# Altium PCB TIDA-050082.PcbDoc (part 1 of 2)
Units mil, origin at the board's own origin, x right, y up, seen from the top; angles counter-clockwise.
Board outline 3622.05 x 2047.24 mil, 6 copper layers (Top Layer, Signal Layer 1, Signal Layer 2, Signal Layer 3, Signal Layer 4, Bottom Layer), stack 61.4 mil thick; 61 components, 29 nets, 139 pads, 38 vias.
Unrouted connection lines stored in the file: 18.
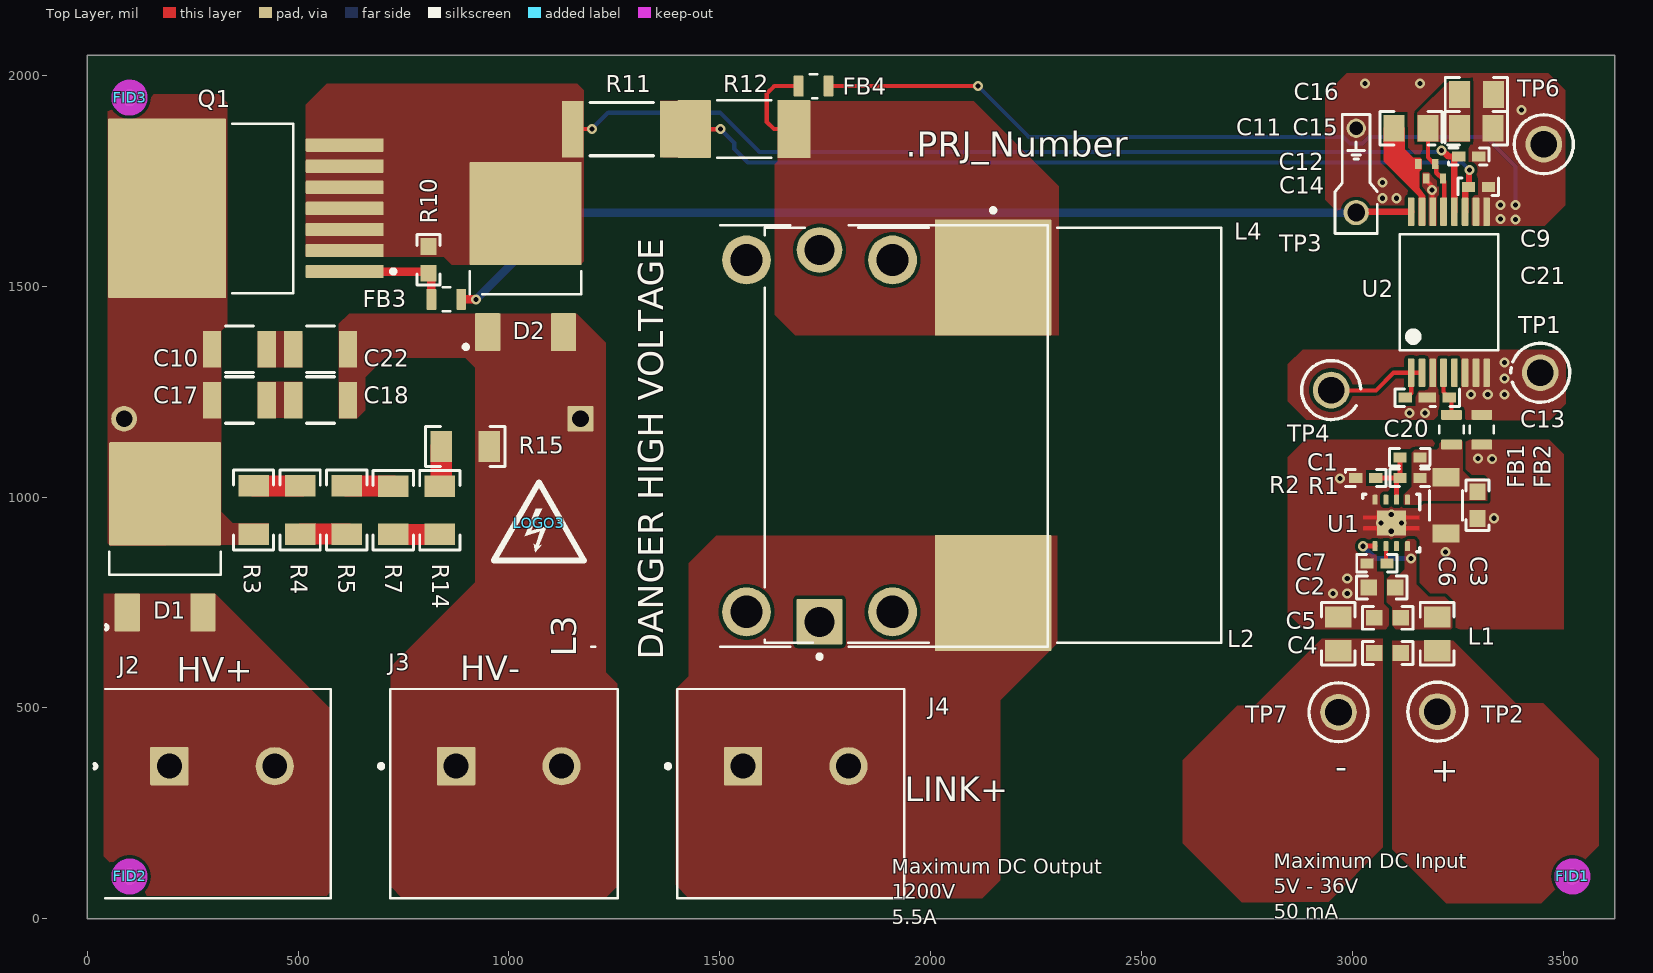
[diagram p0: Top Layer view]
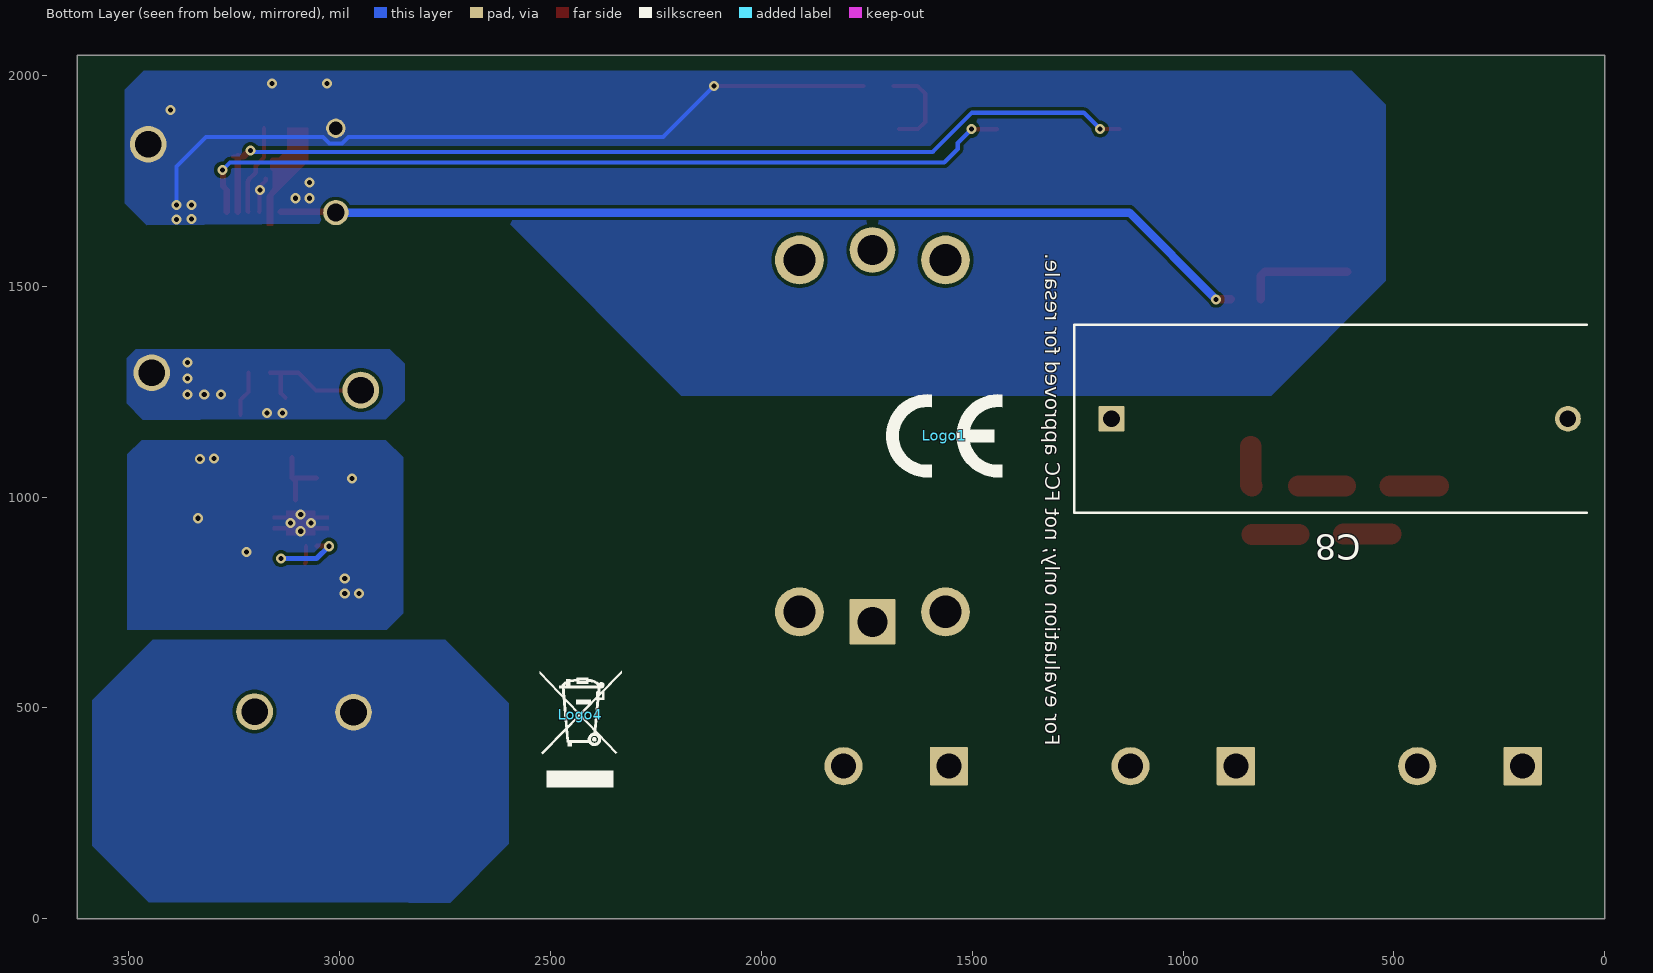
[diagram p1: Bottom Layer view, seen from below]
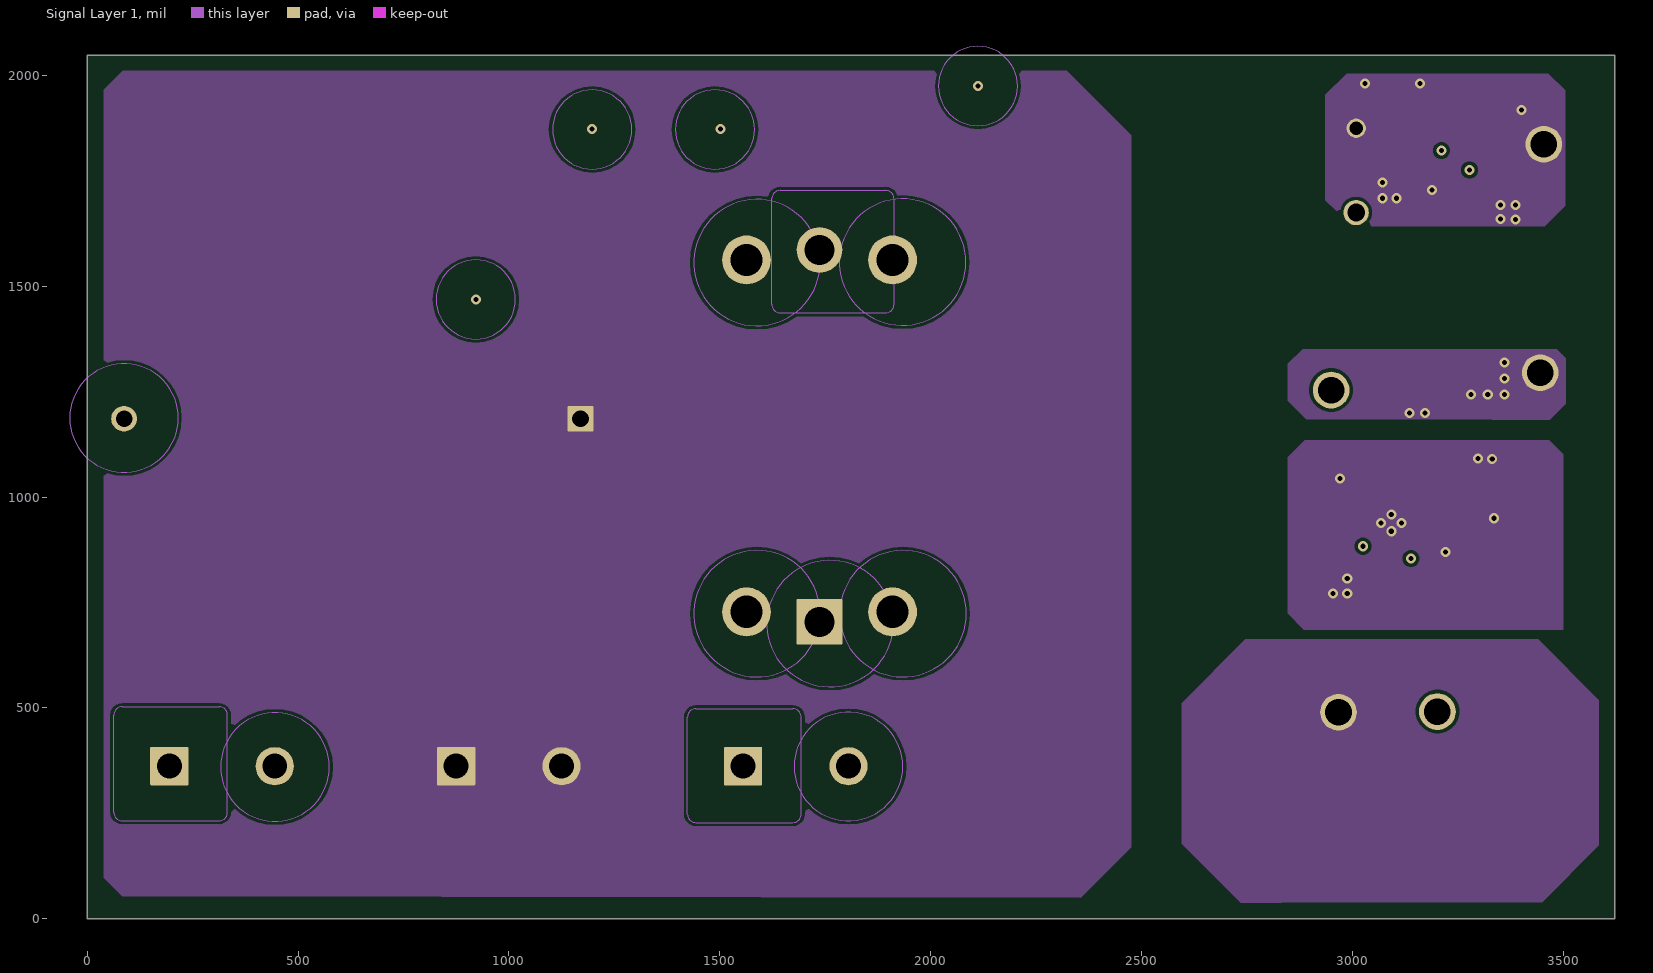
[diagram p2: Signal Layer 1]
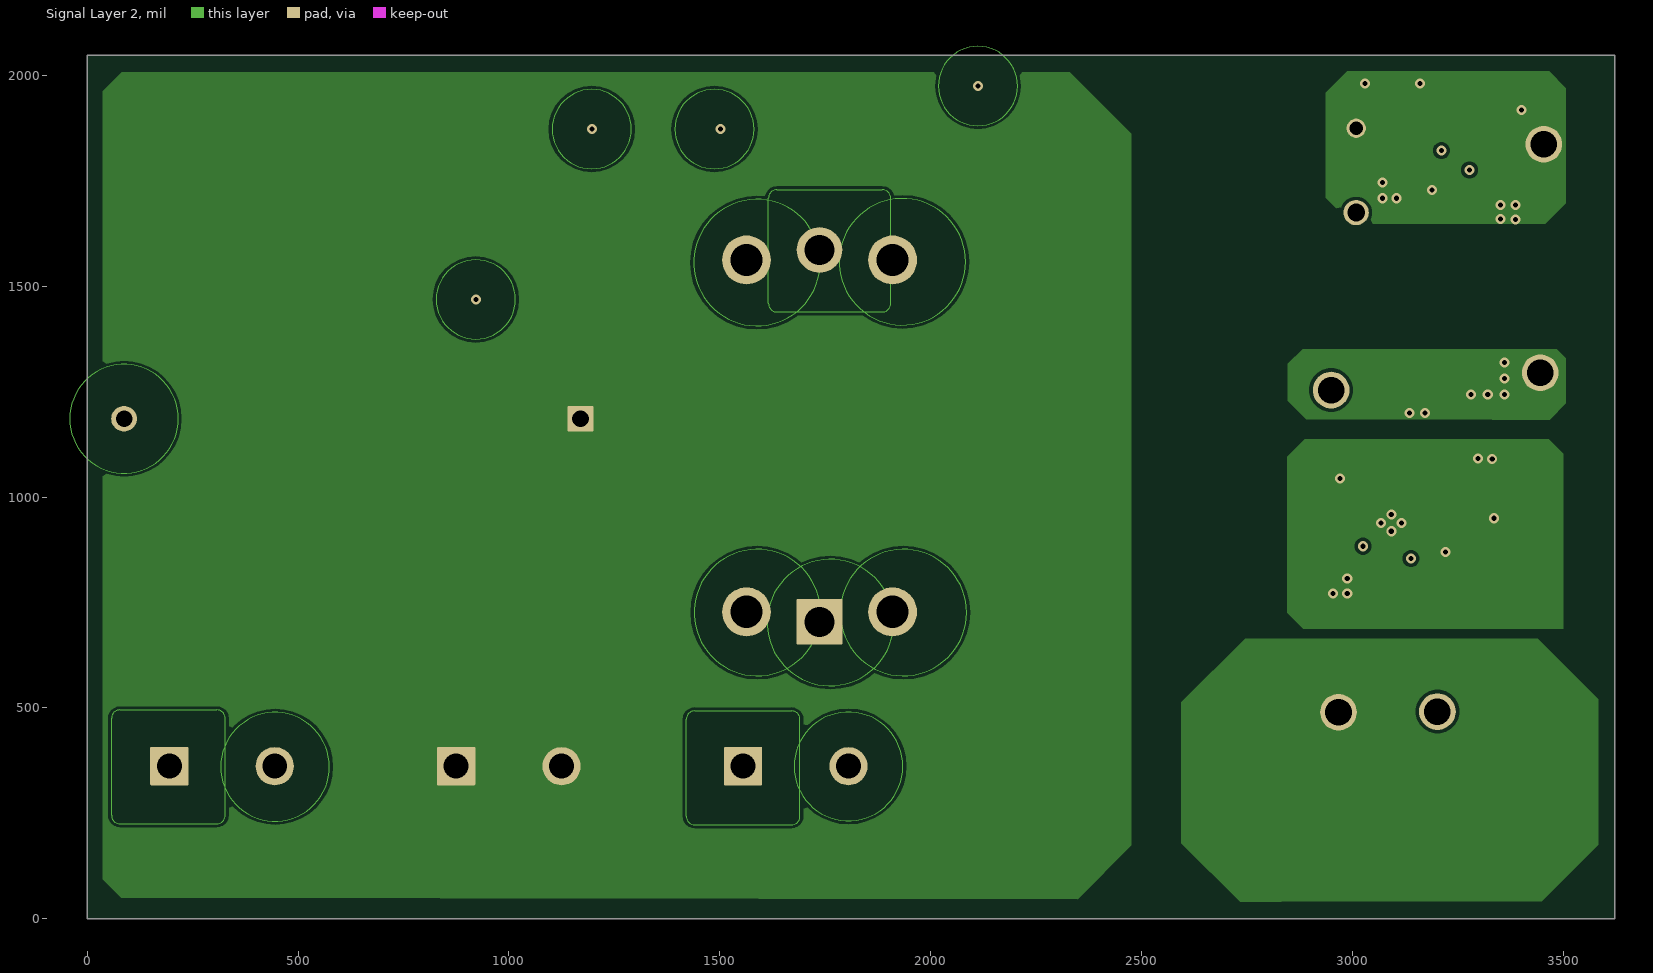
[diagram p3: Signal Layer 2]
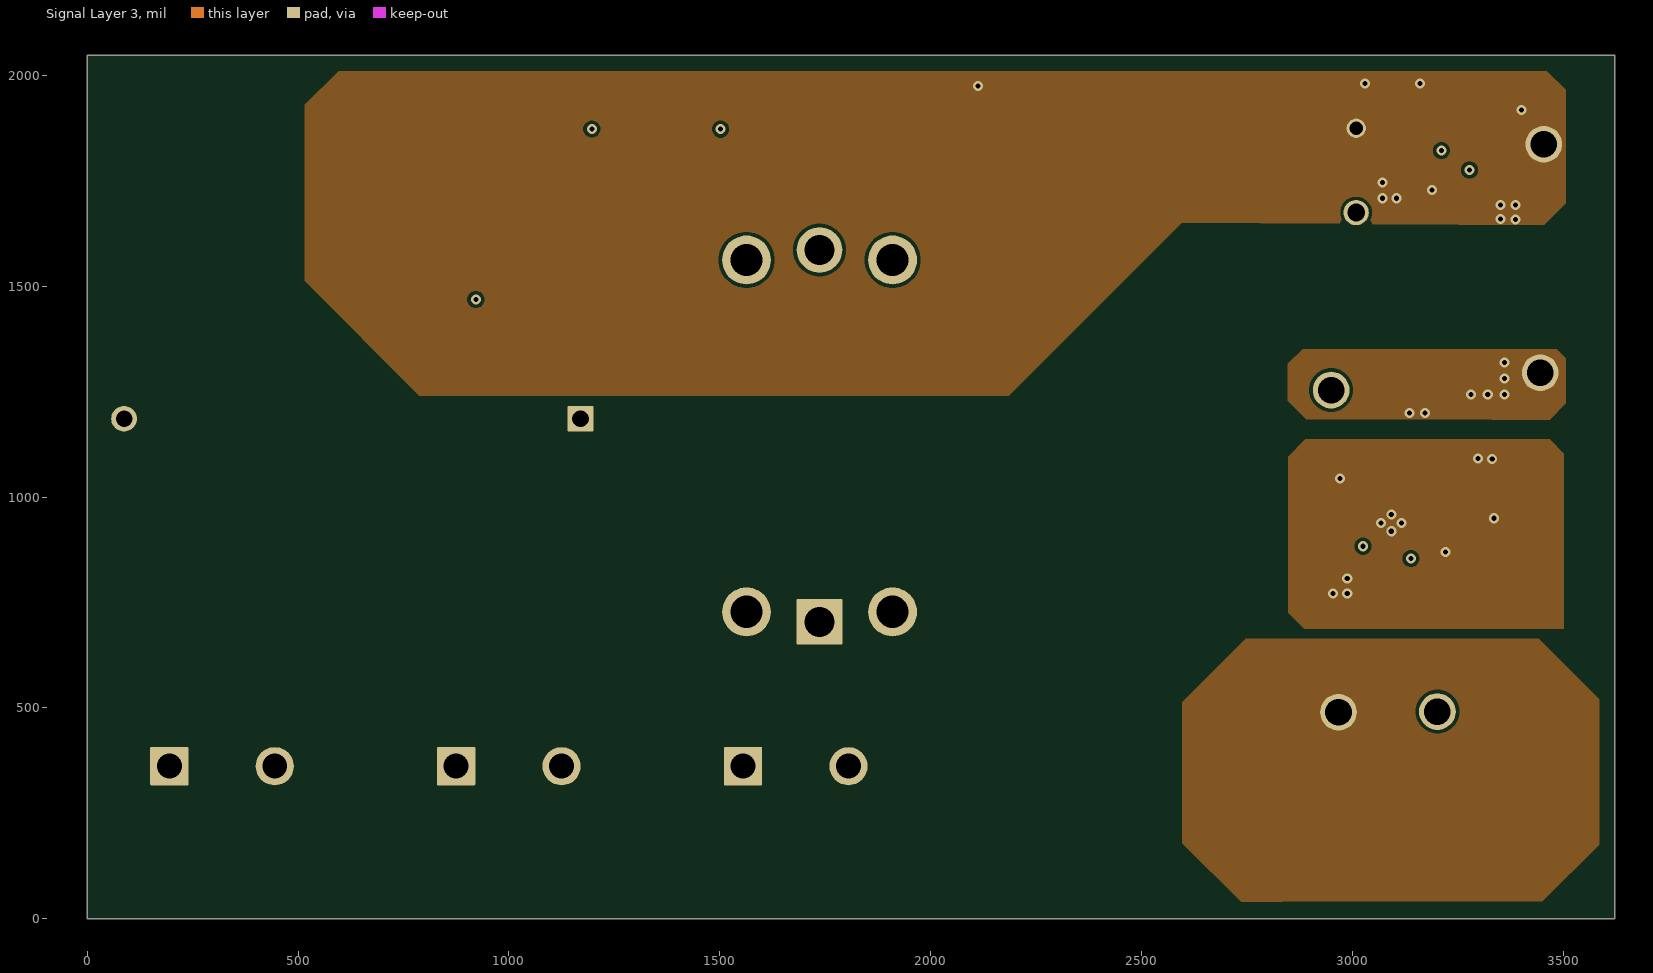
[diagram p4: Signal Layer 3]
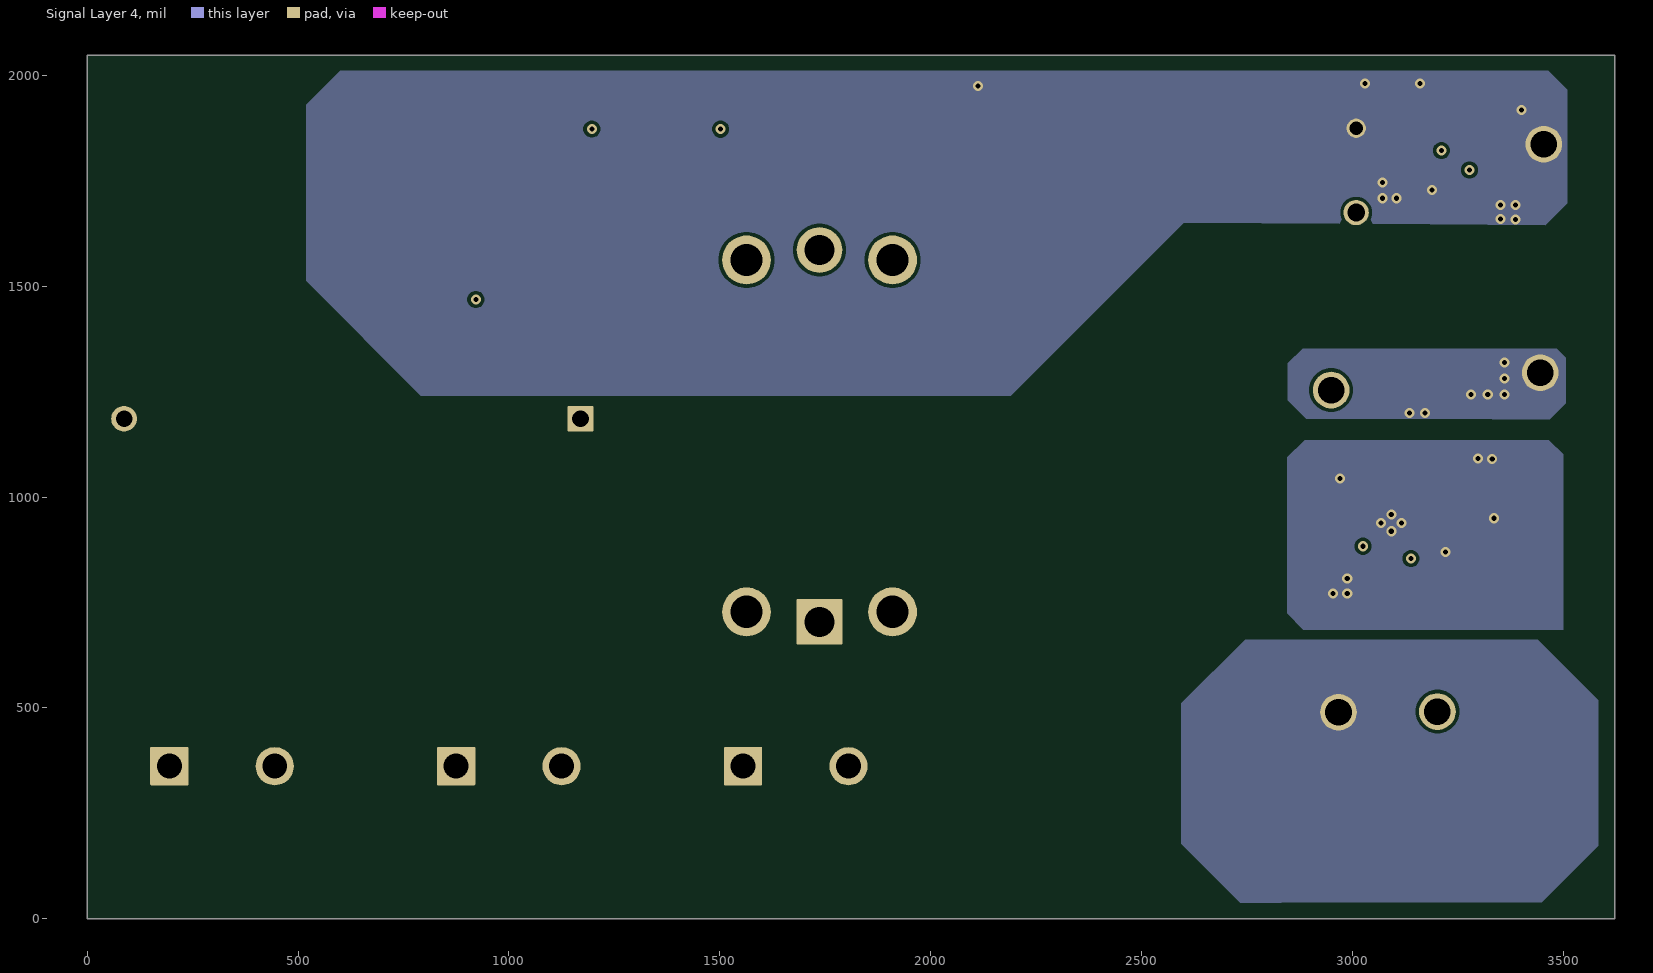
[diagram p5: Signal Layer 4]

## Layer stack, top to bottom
Top Solder: solder mask 0.5, Solder Resist, Dk 3.5
Top Layer: signal copper 2.8
Dielectric 1: prepreg 7, FR-4 High Tg, Dk 4.2
Signal Layer 1: signal copper 1.4
Dielectric 2: core 14, FR-4 High Tg, Dk 4.2
Signal Layer 2: signal copper 1.4
Dielectric 4: prepreg 8.2, FR-4 High Tg, Dk 4.2
Signal Layer 3: signal copper 1.4
Dielectric 5: core 14, FR-4 High Tg, Dk 4.2
Signal Layer 4: signal copper 1.4
Dielectric 3: prepreg 7, FR-4 High Tg, Dk 4.2
Bottom Layer: signal copper 2.8
Bottom Solder: solder mask 0.5, Solder Resist, Dk 3.5

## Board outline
0,0 3622.05,0 3622.05,2047.24 0,2047.24

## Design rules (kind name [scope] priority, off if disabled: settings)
BoardOutlineClearance [All] p1: gap=11.81 ignorepadtopadclearanceinfootprint=FALSE except(15.75: Arc-SplitBarrior Arc-SplitContinuation Track-SplitBarrior Track-SplitContinuation SMDPad-SplitBarrior SMDPad-SplitContinuation THPad-SplitBarrior THPad-SplitContinuation Via-SplitBarrior Via-SplitContinuation Fill-SplitBarrior Fill-SplitContinuation Poly-SplitBarrior Poly-SplitContinuation Region-SplitBarrior Region-SplitContinuation Text-SplitBarrior Text-SplitContinuation)
Clearance "Clearance Different Nets" [All] p1: gap=7.87 ignorepadtopadclearanceinfootprint=FALSE except(3.5: Arc-Arc Arc-Track Arc-SMDPad Track-Track Track-SMDPad; 5: SMDPad-SMDPad SMDPad-Via THPad-Via Via-Via; 10: Arc-Via Arc-Text Track-Via Track-Text SMDPad-Text THPad-Text Via-Text Fill-Text Poly-Text Region-Text Text-Text; 19.68: THPad-THPad Via-Hole)
Clearance "Clearance Same Nets" [All] p2: gap=7.87 ignorepadtopadclearanceinfootprint=FALSE except(3.5: Arc-Arc Arc-Track Arc-SMDPad Track-Track Track-SMDPad SMDPad-SMDPad; 5: SMDPad-Via THPad-Via; 10: Arc-Via Arc-Text Track-Via Track-Text SMDPad-Text THPad-Text Via-Via Via-Text Fill-Text Poly-Text Region-Text Text-Text)
Clearance "Clearance Bottom Layer" [OnLayer('Bottom Layer')] p3: gap=8 ignorepadtopadclearanceinfootprint=TRUE except(10: Arc-Text Track-Text SMDPad-Text THPad-Text Via-Text Fill-Text Poly-Text Region-Text Text-Text)
Clearance "Clearance Top Layer" [OnLayer('Top Layer')] p4: gap=8 ignorepadtopadclearanceinfootprint=TRUE except(10: Arc-Text Track-Text SMDPad-Text THPad-Text Via-Text Fill-Text Poly-Text Region-Text Text-Text)
HoleSize [All] p1: absolutevalues=TRUE maxlimit=248.03 minlimit=7.87 maxpercent=80.000 minpercent=20.000
MinimumAnnularRing [All] p1: minimumring=5.91
MinimumSolderMaskSliver [All] p1: minsoldermaskwidth=3.94
PlaneConnect [All] p1: planeconnectstyle=Direct reliefexpansion=20 reliefentries=4 reliefconductorwidth=10 reliefairgap=10
PolygonConnect PolygonConnect_1 [All] p1: connectstyle=Direct reliefconductorwidth=20 reliefentries=4 polygonreliefangle="90 Angle" airgapwidth=10
RoutingCorners [All] p1: cornerstyle=Round minsetback=100 maxsetback=100
RoutingVias [All] p1: holewidth=19.68 width=39.37 viastyle="Through Hole" minholewidth=7.87 minwidth=13.78 maxholewidth=39.37 maxwidth=78.74
SilkToBoardRegionClearance [Not ((IsComment or IsDesignator) And (Hide <> 'False')) and not InRegion(1000,500,4000,800)] p1:
SilkToSilkClearance [All] p1: silktosilkclearance=3.94
SilkToSolderMaskClearance [IsPad] p1: minsilkscreentomaskgap=3.94 clearancetoexposedcopper=TRUE
SolderMaskExpansion [All] p1: expansion=4 istentingtop=FALSE
SupplyNets "Schematic Supply Nets_4" [InNet('VSSS')] p1: voltage=0.000
SupplyNets "Schematic Supply Nets_3" [InNet('-HV')] p2: voltage=0.000
SupplyNets "Schematic Supply Nets_2" [InNet('+IN')] p3: voltage=0.000
SupplyNets "Schematic Supply Nets_1" [InNet('VSSP')] p4: voltage=0.000
SupplyNets "Schematic Supply Nets" [InNet('V_cap')] p5: voltage=0.000
Width [All] p1: maxlimit=100 minlimit=3.5 preferedwidth=15
23 further rules are at their usual default settings.

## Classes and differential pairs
component class TIDA-050082-Hardware: FID1 FID2 FID3 Logo1 Logo2 LOGO3 Logo4
component class FiducialMark: FID1 FID2 FID3
component class TIDA-050082: C1 C2 C3 C4 C5 C6 C7 C8 C9 C10 C11 C12 C13 C14 C15 C16 C17 C18 C20 C21 C22 D1 D2 FB1 FB2 FB3 FB4 J2 J3 J4 L1 L2 L3 L4 Q1 R1 R2 R3 R4 R5 R7 R10 R11 R12 R14 R15 SH-J? TP1 TP2 TP3 TP4 TP6 TP7 U1 U2 U?

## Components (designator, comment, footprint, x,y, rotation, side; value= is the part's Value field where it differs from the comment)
C1 "GRM155R71E103KA01D" 0402 3136.83,1094.24 r180 top value=0.01uF
C2 "CGA3E2X7R1H104K080AA" 0603 3070.36,785.66 r180 top value=0.1uF
C3 "CGA3E2X7R1H104K080AA" 0603 3297.36,980.66 r270 top value=0.1uF
C4 "GCM188R71H103KA37D" 0603 3083.9,630.25 r180 top value=0.01uF
C5 "GRT188R61E106ME13D" 0603 3083.9,713.64 r180 top value=10uF
C6 "GRM31CR71E106KA12L" 1206_180 3222.36,980.24 r270 top value=10uF
C7 "GRM155R71E103KA01D" 0402 3058.67,842.8 r180 top value=0.01uF
C8 "C4AQSBU4100A1WJ" FP-C4AQSBU4100A1WJ_RADIAL-MFG 628.36,1185.66 r180 bottom value=1µF
C9 "885012205044" 0402 3276.36,1807.66 r0 top value=1000pF
C10 "C1210C104KBRAC7800" 1210_280 360.48,1350.66 r0 top value=0.1uF
C11 "GRM21BZ71E106KE15L" 0805_HV 3139.36,1874.66 r0 top value=10uF
C12 "GRM155R71H103KA88D" 0402S 3176.86,1789.59 r0 top value=0.01uF
C13 "GRM155R71E103KA01D" 0402 3206.36,1235.66 r180 top value=0.01uF
C14 "GRM155R71H103KA88D" 0402S 3195.36,1755.33 r180 top value=0.01uF
C15 "GRM21BZ71E106KE15L" 0805_HV 3293.92,1874.66 r0 top value=10uF
C16 "GRM21BR61E226ME44L" 0805_HV 3294.58,1954.66 r0 top value=22uF
C17 "C1210C104KBRAC7800" 1210_280 360.48,1229.88 r0 top value=0.1uF
C18 "C1210C104KBRAC7800" 1210_280 553.39,1229.88 r0 top value=0.1uF
C20 "GRM155R71E103KA01D" 0402 3149.36,1235.66 r0 top value=0.01uF
C21 "885012205044" 0402 3299.36,1735.66 r0 top value=1000pF
C22 "C1210C104KBRAC7800" 1210_280 553.36,1350.66 r0 top value=0.1uF
D1 "VS-8EWF12SLHM3" FP-VS-8EWF12SLHM3_DPAK-MFG 184.36,905.66 r0 top
D2 "VS-8EWF12SLHM3" FP-VS-8EWF12SLHM3_DPAK-MFG 1039.36,1570.66 r0 top
FB1 "BLM21HE802SH1L" FP-BLM21HE802SH1L_0805-MFG 3235.36,1159.66 r90 top
FB2 "BLM21HE802SH1L" FP-BLM21HE802SH1L_0805-MFG 3307.36,1159.66 r90 top
FB3 "BLM21HE802SH1L" FP-BLM21HE802SH1L_0805-MFG 851.36,1468.66 r180 top
FB4 "BLM21HE802SH1L" FP-BLM21HE802SH1L_0805-MFG 1722.36,1974.66 r180 top
FID1 "Fiducial" Fiducial10-20 3522.05,100 r90 top
FID2 "Fiducial" Fiducial10-20 100,100 r90 top
FID3 "Fiducial" Fiducial10-20 100,1947.24 r90 top
J2 "691250610002" FP-691250610002_CONN_TERM_BLOCK2-MFG 307.55,296.66 r0 top
J3 "691250610002" FP-691250610002_CONN_TERM_BLOCK2-MFG 987.95,296.66 r0 top
J4 "691250610002" FP-691250610002_CONN_TERM_BLOCK2-MFG 1668.36,296.66 r0 top
L1 "BLM21AG102SN1D" 0805_HV 3201.31,675.4 r90 top value="1000 ohm"
L2 "BLM21AG102SN1D" 0805_HV 2966.61,675.4 r90 top value="1000 ohm"
L3 "ZG3718" FP-ZG3718_PTH6-MFG 1736.58,1145 r90 top value=100uH
L4 "ZF3172-AE" FP-ZF3172-AE_SMD2-MFG 2148.36,1146.66 r270 top value=100uH
Logo1 "CE Mark" CE_Mark_5mm 1566.36,1145 r180 bottom
Logo2 "FCC disclaimer" FCC_disclaimer 4048.02,567.94 r90 top
LOGO3 "DANGER HIGH VOLTAGE" IEC_HighVoltage_Small 1071,937.69 r0 top
Logo4 "WEEE logo" WEEE_Minimum 2430,483.63 r180 bottom
Q1 "AIMBG120R160M1XTMA1" FP-AIMBG120R160M1XTMA1_TO263-7-MFG 302.36,1684.66 r90 top
R1 "ERJ-2RKF2943X" 0402 3137.15,1045.66 r0 top value=294k
R2 "ERJ-2RKF9092X" 0402 3032.1,1045.11 r0 top value=90.9k
R3 "CRCW1206180KJNEA" 1206 394.3,969.19 r270 top value=180k
R4 "CRCW1206180KJNEA" 1206 504.71,969.19 r90 top value=180k
R5 "CRCW1206180KJNEA" 1206 615.13,969.19 r270 top value=180k
R7 "CRCW1206180KJNEA" 1206 725.54,968.66 r90 top value=180k
R10 "ERJ-3GEYJ104V" 0603 809.36,1562.66 r270 top value=100k
R11 "WSL2512R0600FEA" 2512 1267.61,1872.66 r180 top value=0.06
R12 "TLRP3A20CR080FTE" FP-TLRP3A20CR080FTE_2512-MFG 1557.61,1872.66 r180 top value=80m
R14 "CRCW1206180KJNEA" 1206 835.95,968.66 r270 top value=180k
R15 "CRCW1206180KJNEA" 1206 896.36,1119.66 r180 top value=180k
TP1 "5011" Keystone5011 3446,1294.72 r0 top
TP2 "" Keystone5010 3202,491 r0 top
TP3 "TESTPOINT_PIGTAIL" TESTPOINT_PIGTAIL 3009.36,1674.66 r180 top
TP4 "EN" Keystone5014 2950,1253.66 r0 top
TP6 "5011" Keystone5011 3454.36,1836.66 r0 top
TP7 "5011" Keystone5011 2967.36,489.64 r0 top
U1 "TPS7A4901DRBR" DRB0008A 3092.58,938.49 r270 top
U2 "TPSI31P1QDVXRQ1" DVX0016A-MFG 3229.36,1485.66 r90 top

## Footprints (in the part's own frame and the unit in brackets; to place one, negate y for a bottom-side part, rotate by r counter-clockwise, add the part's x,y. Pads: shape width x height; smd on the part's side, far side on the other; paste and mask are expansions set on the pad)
0402 [mm] "0402 from SM-752 data"
  rect 0.8x0.6 smd: 1(-0.6,0) 2(0.6,0)
  silkscreen extent -1.22,-0.52 1.22,0.52, body extent -0.55,-0.3 0.55,0.3, height 0.6
0402S [mil] "Based on C0402S footprint from PADS legacy"
  rect 15x24 smd: 1(-20,0) 2(20,0)
  body extent -22,-12 22,12, height 24
0603 [mm] "0603 from SM-752 data"
  rect 1x0.95 smd: 1(-0.8,0) 2(0.8,0)
  silkscreen extent -1.52,-0.69 1.52,0.69, body extent -0.87,-0.47 0.87,0.47, height 1
0805_HV [mil] "0805 with 30mil clearance between pads"
  rect 50x63 smd: 1(-40,0) 2(40,0)
  silkscreen extent -74,-40 74,40, body extent -43,-29 43,29, height 57
1206 [mm] "1206 from SM-752 data"
  rect 1.3x1.85 smd: 1(-1.45,0) 2(1.45,0)
  silkscreen extent -2.4,-1.21 2.4,1.21, body extent -1.7,-0.9 1.7,0.9, height 1.35
1206_180 [mm] "1206_180"
  rect 1.1x1.6 smd: 1(-1.7,0) 2(1.7,0)
  silkscreen extent -0.9,-1 0.9,1, body extent -1.75,-0.95 1.75,0.95, height 1.8
1210_280 [mm] "SMD, 2-Leads, Body 3.6x2.8mm, Height 2.8mm"
  rect 1.1x2.2 smd: 1(-1.65,0) 2(1.65,0)
  silkscreen extent -0.84,-1.4 0.84,1.4, body extent -1.8,-1.4 1.8,1.4, height 2.8
2512 [mm] "Chip Resistor, Body 6.3x3.2mm, IPC Medium Density"
  rect 1.3x3.4 smd: 1(-2.95,0) 2(2.95,0)
  silkscreen extent -1.9,-1.6 1.9,1.6, body extent -3.22,-1.67 3.22,1.67, height 0.71
CE_Mark_5mm [mil] "Minimum text height for CE Mark"
  silkscreen extent -138,-98 138,98
DRB0008A [mm] "VSON-8"
  rrect32% 0.6x0.31 smd: 1(-1.4,0.975) 2(-1.4,0.325) 3(-1.4,-0.325) 4(-1.4,-0.975) 5(1.4,-0.975) 6(1.4,-0.325) 7(1.4,0.325) 8(1.4,0.975)
  rrect7% 1.5x1.75 smd paste-0.75: 9(0,0)
  Top Layer region: -0.7,-0.875 -0.49,-0.875 -0.471,-0.879 -0.455,-0.89 -0.444,-0.906 -0.44,-0.925 -0.44,-0.925 -0.44,-1.65 -0.436,-1.669 -0.425,-1.685 -0.409,-1.696 -0.39,-1.7 -0.39,-1.7 -0.26,-1.7 -0.241,-1.696 -0.225,-1.685 -0.214,-1.669 -0.21,-1.65 -0.21,-1.65 -0.21,-0.925 -0.206,-0.906 -0.195,-0.89 -0.179,-0.879 -0.16,-0.875 -0.16,-0.875 0.16,-0.875 0.179,-0.879 0.195,-0.89 0.206,-0.906 0.21,-0.925 0.21,-0.925 0.21,-1.65 0.21,-1.65 0.214,-1.669 0.225,-1.685 0.241,-1.696 0.26,-1.7 0.26,-1.7 0.39,-1.7 0.409,-1.696 0.425,-1.685 0.436,-1.669 0.44,-1.65 0.44,-1.65 0.44,-0.925 0.444,-0.906 0.455,-0.89 0.471,-0.879 0.49,-0.875 0.49,-0.875 0.7,-0.875 0.719,-0.871 0.735,-0.86 0.746,-0.844 0.75,-0.825 0.75,-0.825 0.75,0.825 0.746,0.844 0.735,0.86 0.719,0.871 0.7,0.875 0.7,0.875 0.49,0.875 0.471,0.879 0.455,0.89 0.444,0.906 0.44,0.925 0.44,0.925 0.44,1.65 0.436,1.669 0.425,1.685 0.409,1.696 0.39,1.7 0.39,1.7 0.26,1.7 0.241,1.696 0.225,1.685 0.214,1.669 0.21,1.65 0.21,1.65 0.21,1.65 0.21,0.925 0.206,0.906 0.195,0.89 0.179,0.879 0.16,0.875 0.16,0.875 -0.16,0.875 -0.179,0.879 -0.195,0.89 -0.206,0.906 -0.21,0.925 -0.21,0.925 -0.21,1.65 -0.214,1.669 -0.225,1.685 -0.241,1.696 -0.26,1.7 -0.26,1.7 -0.39,1.7 -0.409,1.696 -0.425,1.685 -0.436,1.669 -0.44,1.65 -0.44,1.65 -0.44,0.925 -0.444,0.906 -0.455,0.89 -0.471,0.879 -0.49,0.875 -0.49,0.875 -0.7,0.875 -0.719,0.871 -0.735,0.86 -0.746,0.844 -0.75,0.825 -0.75,0.825 -0.75,-0.825 -0.746,-0.844 -0.735,-0.86 -0.719,-0.871 -0.7,-0.875
  silkscreen extent -1.73,-1.73 1.73,1.73, body extent -1.5,-1.5 1.5,1.5, height 0.77
DVX0016A-MFG [mm]
  rrect24% 1.7x0.41 smd paste+0 mask+0: 1(-4.85,2.275) 2(-4.85,1.625) 3(-4.85,0.975) 4(-4.85,0.325) 5(-4.85,-0.325) 6(-4.85,-0.975) 7(-4.85,-1.625) 8(-4.85,-2.275) 9(4.85,-2.275) 10(4.85,-1.625) 11(4.85,-0.975) 12(4.85,-0.325) 13(4.85,0.325) 14(4.85,0.975) 15(4.85,1.625) 16(4.85,2.275)
  silkscreen extent -3.5,-2.98 3.5,2.98, body extent -5.8,-3.22 5.8,3.22, height 0.25
FCC_disclaimer [mil]
Fiducial10-20 [mm]
  round 1 smd mask+0.5: 1(0,0)
  Top Layer keep-out circle w1.178: c0,0 r0.5
FP-691250610002_CONN_TERM_BLOCK2-MFG [mm]
  rrect4% 2.3x2.3 hole 1.5 paste-2539.97 mask+0: 1(-2.875,1.65)
  round 2.3 hole 1.5 paste-2539.97 mask+0: 2(3.475,1.65)
  silkscreen extent -7.39,-6.3 6.85,6.3, body extent -6.95,-6.4 6.95,6.4, height 0.25
FP-AIMBG120R160M1XTMA1_TO263-7-MFG [mm] "Recommended Land Pattern"
  rrect13% 0.8x4.7 smd paste-1000 mask+0: 1(-3.81,-7.825) 2(-2.54,-7.825) 3(-1.27,-7.825) 4(0,-7.825) 5(1.27,-7.825) 6(2.54,-7.825) 7(3.81,-7.825)
  rrect1% 10.8x7.1 smd paste-1000 mask+0: 8(0,2.875)
  silkscreen extent -5.1,-10.87 5.1,-1.05, body extent -5.5,-10.28 5.5,6.53, height 0.25
FP-BLM21HE802SH1L_0805-MFG [mm] "Recommended Land Pattern"
  rrect17% 0.6x1.25 smd paste+0 mask+0: 1(-0.9,0) 2(0.9,0)
  silkscreen extent -0.23,-0.72 0.23,0.72, body extent -1,-0.63 1,0.63, height 1.45
FP-C4AQSBU4100A1WJ_RADIAL-MFG [mm]
  rrect6% 1.55x1.55 hole 1 paste-2539.97 mask+0: 1(-13.75,0)
  round 1.55 hole 1 paste-2539.97 mask+0: 2(13.75,0)
  silkscreen extent -16,-5.65 14.89,5.65, body extent -15.75,-5.5 15.75,5.5, height 20.2
FP-TLRP3A20CR080FTE_2512-MFG [mm] "Recommended Land Pattern"
  rrect5% 2x3.5 smd paste+0 mask+0: 1(-3,0) 2(3,0)
  silkscreen extent -1.63,-1.73 1.63,1.73, body extent -3.2,-1.6 3.2,1.6, height 0.9
FP-VS-8EWF12SLHM3_DPAK-MFG [mm] "Recommended Land Pattern"
  rrect7% 1.524x2.28 smd paste+0 mask+0: 1(-2.28,-4.56) 3(2.28,-4.56)
  rrect2% 6.74x6.23 smd paste+0 mask+0: 4(0,2.585)
  silkscreen extent -3.56,-5.57 3.36,-0.9, body extent -3.27,-4.95 3.27,4.95, height 2.52
FP-ZF3172-AE_SMD2-MFG [mm] "Recommended Land Pattern"
  rrect1% 7x7 smd paste+0 mask+0: 1(-9.5,0) 2(9.5,0)
  silkscreen extent -13.67,-13.75 12.5,13.75, body extent -13.1,-13.85 13.1,13.85, height 0.25
FP-ZG3718_PTH6-MFG [mm] "Recommended Land Pattern"
  rrect4% 2.753x2.753 hole 1.803 paste-2539.97 mask+0: 1(-11.2,0)
  round 2.753 hole 1.803 paste-2539.97 mask+0: 2(11.2,0)
  round 2.943 hole 1.943 paste-2539.97 mask+0: 3(-10.6,4.4) 4(10.6,4.4) 5(-10.6,-4.4) 6(10.6,-4.4)
  silkscreen extent -13.42,-13.75 12.7,13.75, body extent -12.7,-13.75 12.7,13.75, height 21.5
IEC_HighVoltage_Small [mil]
  silkscreen extent -107,-88 107,97
Keystone5010 [mil] "Keystone Multipurpose loops"
  round 87 hole 63: 1(0,0)
  silkscreen extent -70,-70 70,70, body extent -63,-63 63,62, height 319
Keystone5011 [mil] "Keystone Multipurpose loops"
  round 87 hole 63: 1(0,0)
  silkscreen extent -70,-70 70,70, body extent -63,-63 63,62, height 319
Keystone5014 [mil] "Keystone Multipurpose loops"
  round 87 hole 63: 1(0,0)
  silkscreen extent -70,-70 70,70, body extent -63,-63 63,62, height 319
TESTPOINT_PIGTAIL [mil] "Pigtail"
  round 60 hole 42: 1(0,0)
  round 46 hole 32: 2(0,-200)
  silkscreen extent -50,-233 50,50
WEEE_Minimum [mil] "WEEElie bin"
  silkscreen extent -95,-172 99,104

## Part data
C1 C7 C13 C20: library part CMP-0006658-2, "CAP, CERM, 0.01 uF, 25 V, +/- 10%, X7R, 0402", Cap_Case=0402, Manufacturer=MuRata, Supplier Part Number 1=490-1312-1-ND, TempCo=X7R, Tolerance_%=10%, Value1=Unknown, Value2=25V, ValueDisplayed=0.01uF
C2 C3: library part CMP-0007078-4, "CAP, CERM, 0.1 uF, 50 V, +/- 10%, X7R, AEC-Q200 Grade 1, 0603", Cap_Case=0603, Manufacturer=TDK, Supplier Part Number 1=445-5666-1-ND, TempCo=X7R, Tolerance_%=10%, Value1="0.0296 ohm", Value2=50V, ValueDisplayed=0.1uF
C4: library part CMP-0007143-4, "CAP, CERM, 0.01 uF, 50 V, +/- 10%, X7R, AEC-Q200 Grade 1, 0603", Cap_Case=0603, Manufacturer=MuRata, Supplier Part Number 1=490-4778-1-ND, TempCo=X7R, Tolerance_%=10%, Value1=Unknown, Value2=50V, ValueDisplayed=0.01uF
C5: library part CMP-0007501-5, "CAP, CERM, 10 uF, 25 V, +/- 20%, X5R, 0603", Cap_Case=0603, Manufacturer=MuRata, Supplier Part Number 1=490-12323-1-ND, TempCo=X5R, Tolerance_%=20%, Value1=Unknown, Value2=25V, ValueDisplayed=10uF
C6: library part CMP-0008965-2, "CAP, CERM, 10 uF, 25 V, +/- 10%, X7R, 1206", Cap_Case=2220, Manufacturer=MuRata, Supplier Part Number 1=81-GRM31CR71E106KA12, TempCo=X7R, Tolerance_%=10%, Value1=Unknown, Value2=25V, ValueDisplayed=10uF
C8: library part CMP-0122633-1, "1 µF Film Capacitor 1500V (1.5kV) Polypropylene (PP), Metallized Radial", Digikey Part Number=399-16944-ND, Manufacturer=KEMET, Mouser Part Number=80-C4AQSBU4100A1WJ, Operating Temperature Range="-55°C to +105°C", Tolerance_%=5%, ValueDisplayed=1uF
C9 C21: library part CMP-0006229-2, "CAP, CERM, 1000 pF, 25 V, +/- 10%, X7R, 0402", Cap_Case=0402, Manufacturer="Wurth Elektronik", Supplier Part Number 1=710-885012205044, TempCo=X7R, Tolerance_%=10%, Value1=Unknown, Value2=25V, ValueDisplayed=1000pF
C10 C17 C18 C22: library part CMP-0009076-1, "CAP, CERM, 0.1 uF, 630 V, +/- 10%, X7R, 1210", Cap_Case=1210, Manufacturer=Kemet, Supplier Part Number 1=399-13490-1-ND, TempCo=X7R, Tolerance_%=10%, Value1=Unknown, Value2=630V, ValueDisplayed=0.1uF
C11 C15: library part CMP-0008378-2, "CAP, CERM, 10 uF, 25 V, +/- 10%, X7R, 0805", Cap_Case=0805, Manufacturer=MuRata, Supplier Part Number 1=81-GRM21BZ71E106KE5L, TempCo=X7R, Tolerance_%=10%, Value1=Unknown, Value2=25V, ValueDisplayed=10uF
C12 C14: library part CMP-0006674-2, "CAP, CERM, 0.01 uF, 50 V, +/- 10%, X7R, 0402", Cap_Case=0402, Manufacturer=MuRata, Supplier Part Number 1=490-4516-1-ND, TempCo=X7R, Tolerance_%=10%, Value1=Unknown, Value2=50V, ValueDisplayed=0.01uF
C16: library part CMP-0008305-2, "CAP, CERM, 22 uF, 25 V, +/- 20%, X5R, 0805", Cap_Case=0805, Manufacturer=MuRata, Supplier Part Number 1=490-10749-1-ND, TempCo=X5R, Tolerance_%=20%, Value1=Unknown, Value2=25V, ValueDisplayed=22uF
D1 D2: library part CMP-0127376-1, "Diode 1200 V 8A Surface Mount TO-252AA (DPAK)", Digikey Part Number=VS-8EWF12SLHM3GICT-ND, Forward Current=8A, Manufacturer=Vishay, Max Surge Forward Current=150A, Mouser Part Number=78-VS-8EWF12SLHM3, Operating Temperature Range="-40°C to +150°C", Peak Reverse Current=0.1mA
FB1 FB2 FB3 FB4: library part CMP-0126464-1, "8 kOhms @ 100 MHz 1 Signal Line Ferrite Bead 0805 (2012 Metric) 650mA 700mOhm", Digikey Part Number=490-BLM21HE802SH1LCT-ND, Impedance At Frequency="8000Ω @ 100MHz", Manufacturer=Murata, Mouser Part Number=81-BLM21HE802SH1L, Operating Temperature Range="-55°C to +125°C", Test Frequency=100MHz, Tolerance_%=25%
FID1 FID2 FID3: library part CMP-0077181-1, "Fiducial mark.  There is nothing to buy or mount.", Manufacturer=N/A
J2 J3 J4: library part CMP-0093233-2, "2 Position Wire to Board Terminal Block Horizontal with Board 0.250\" (6.35mm) Through Hole", Current_A=32A, Digikey Part Number=732-691250610002-ND, Manufacturer="Wurth Electronics", Mouser Part Number=710-691250610002, Operating Temperature Range="-32°C to +120°C", Voltage_V=450V
L1 L2: library part CMP-0003356-1, "Ferrite Bead, 1000 ohm @ 100 MHz, 0.5 A, 0805", Manufacturer=MuRata, Supplier Part Number 1=490-1041-1-ND, Value1="0.28 ohm", Value2=0.5A, ValueDisplayed="1000 ohm"
L3: library part CMP-0127410-1, "Power inductor, 100uH-9.6A, Flat wire, TH, PQ26", Manufacturer=Coilcraft, Operating Temperature Range=to, Test Frequency=100kHz, Tolerance_%=10%
L4: library part CMP-0124608-1, "Power inductor, PQ26, SMD", Manufacturer=Coilcraft, Operating Temperature Range=to, Test Frequency=100kHz, Tolerance_%=10%
Logo1: library part CMP-0074844-1
Logo2: library part CMP-0074847-1, "FCC_disclaimer"
LOGO3: library part CMP-0074835-1, "IEC 61010-1 High Voltage Warning"
Logo4: library part CMP-0074769-1
Q1: library part CMP-0124671-1, "N-Channel 1200 V 17A (Tc) 106W (Tc) Surface Mount PG-TO263-7-12", Digikey Part Number=448-AIMBG120R160M1XTMA1CT-ND, Input Capacitance At Vds="350pF @ 800V", Manufacturer=Infineon, Mouser Part Number=726-AIMBG120R160M1X1, Operating Temperature Range="-55°C to +175°C", Power_W=106W, Pulse Drain Current=43A, Typ Forward Diode Voltage=3.9V
R1: library part CMP-0026693-1, "RES, 294 k, 1%, 0.1 W, AEC-Q200 Grade 0, 0402", Manufacturer=Panasonic, Power_W=100mW, Supplier Part Number 1=P294KLCT-ND, TempCo="100 ppm/C", Tolerance_%=1%, Value2=0.1W, Value_Code=294k
R2: library part CMP-0026711-1, "RES, 90.9 k, 1%, 0.1 W, AEC-Q200 Grade 0, 0402", Manufacturer=Panasonic, Power_W=100mW, Supplier Part Number 1=P90.9KLCT-ND, TempCo="100 ppm/C", Tolerance_%=1%, Value2=0.1W, Value_Code=90k9, ValueDisplayed=90.9k
R3 R4 R5 R7 R14 R15: library part CMP-0018599-3, "RES, 180 k, 5%, 0.25 W, AEC-Q200 Grade 0, 1206", Manufacturer=Vishay-Dale, Power_W=250mW, Supplier Part Number 1=541-180KECT-ND, TempCo="200 ppm/C", Tolerance_%=5%, Value2=0.25W, Value_Code=180k
R10: library part CMP-0025875-3, "RES, 100 k, 5%, 0.1 W, AEC-Q200 Grade 0, 0603", Manufacturer=Panasonic, Power_W=100mW, Supplier Part Number 1=P100KGCT-ND, TempCo="200 ppm/C", Tolerance_%=5%, Value2=0.1W, Value_Code=100k
R11: library part CMP-0015855-2, "RES, 0.06, 1%, 1 W, 2512", Manufacturer=Vishay-Dale, Power_W=1W, Supplier Part Number 1=WSLG-.06CT-ND, TempCo="75 ppm/C", Tolerance_%=1%, Value_Code=R060, ValueDisplayed=0.06
R12: library part CMP-0126009-1, "80 mOhms ±1% 2W Chip Resistor 2512 (6432 Metric) Anti-Sulfur, Automotive AEC-Q200, Current Sense Metal Element", Digikey Part Number=1712-TLRP3A20CR080FTECT-ND, Manufacturer="TE Connectivity", Mouser Part Number=279-TLRP3A20CR080FTE, Operating Temperature Range="-55°C to +170°C", Power_W=2W, TempCo=25ppm/°C, Tolerance_%=1%
TP1 TP6 TP7: library part CMP-0055148-2, "Test Point, Multipurpose, Black, TH", Color=Black, Manufacturer="Keystone Electronics", Supplier Part Number 1=36-5011-ND
TP2: library part CMP-0055147-2, "Test Point, Multipurpose, Red, TH", Color=Red, Manufacturer="Keystone Electronics", PartNumber=5010, Supplier Part Number 1=36-5010-ND
TP3: library part CMP-0003907-1, "PIGTAIL", Manufacturer="Texas Instruments"
TP4: library part CMP-0055151-2, "Test Point, Multipurpose, Yellow, TH", Color=Yellow, Manufacturer="Keystone Electronics", PartNumber=5014, Supplier Part Number 1=36-5014-ND
U1: library part CMP-0073868-3, "Vin 3V to 36V, 150mA, Ultra-Low-Noise, High-PSRR Low-Dropout (LDO) Linear Regulator, DRB0008A (VSON-8)", Alternate Manufacturer="Texas Instruments", Alternate PartNumber=TPS7A4901DRBT, Operating Temperature Range="-40 to 125 C", Rating=Catalog
U2: library part CMP-0122535-1, "Isolated Automotive Active Pre-charge Controller with Integrated Gate Driver and Bias Supply", Manufacturer="Texas Instruments", Max Power Dissipation=250mW, Max Supply Voltage=5.5V, Min Supply Voltage=4.5V, Nominal Supply Current=5.3-35mA, Operating Temperature Range="-40°C to +150°C", Output Voltage=15.8V

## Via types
v1: diameter 23.82, hole 12, Top Layer to Bottom Layer, 38 vias

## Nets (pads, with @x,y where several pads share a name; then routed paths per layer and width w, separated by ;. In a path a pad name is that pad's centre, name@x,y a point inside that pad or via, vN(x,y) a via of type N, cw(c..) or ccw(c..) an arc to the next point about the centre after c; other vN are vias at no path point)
1.23Vcmp: C9.1 D2.4 Q1.2 Q1.3 Q1.4 Q1.5 Q1.6 Q1.7 R10.1 R11.2 U2.12 | length 2295
  Top Layer w10: R11.2@1151.47,1872.66 v1(1196.36,1872.66) ; C9.1@3242.02,1807.66 C9.1@3252.74,1807.66
  Top Layer w15: v1(3211.34,1821.66) 3214.32,1821.66 3228.32,1807.66 C9.1@3242.02,1807.66 ; U2.12@3242.15,1676.61 C9.1@3242.15,1808.58
  Bottom Layer w10: v1(1196.36,1872.66) 1235.36,1911.66 1500.77,1911.66 1593.77,1818.66 3208.34,1818.66 v1(3211.34,1821.66)
160mVcmp: C21.1 R11.1 R12.2 U2.11 | length 1989
  Top Layer w10: R12.2@1441.47,1872.66 1441.75,1872.38 v1(1502,1872.38) ; C21.1@3267.74,1727.67 C21.1@3275.74,1735.66 C21.1@3275.25,1736.15
  Top Layer w15: U2.11@3267.74,1676.61 C21.1@3267.74,1727.67 ; C21.1@3275.25,1736.15 3276.91,1737.81 3276.91,1774.6 v1(3278.07,1775.77)
  Bottom Layer w10: v1(1502,1872.38) 1534.39,1839.99 1534.39,1825.63 1566.36,1793.66 3260.19,1793.66 v1(3278.07,1775.77)
+HV: D1.1 D1.3 J2.1 J2.2
+IN: C8.2 C10.1 C17.1 D1.4 Q1.8 R3.2
-HV: C8.1 C18.2 C22.2 D2.1 D2.3 J3.1 J3.2 R15.1
EN: C20.1 TP4.1 U2.1 U2.2 | length 295
  Top Layer w10: TP4.1@2951,1253 3056.17,1253 3097.89,1294.72 U2.1@3139.79,1294.72 ; C20.1@3129.36,1235.66 3139.79,1246.09 U2.1@3139.79,1294.72 ; U2.2@3165.38,1294.72 U2.1@3139.79,1294.72
LDO_GND: C2.2 C3.2 C5.2 C6.2 C7.2 FB2.1 L2.2 R2.1 U1.4 U1.9
  other v1: 2954,771.69 2988.14,771.66 2988.14,806.66 3221.17,869.62 3092.58,918.81 3067.97,938.49 3117.19,938.49 3336.36,949.66 3092.58,958.18 2971.36,1043.8 3332.01,1090.09 3298,1091
LDO_INPUT+: C4.1 L1.1 TP2.1
LDO_INPUT-: C4.2 L2.1 TP7.1
LDO_OUT: C1.1 C3.1 C6.1 FB1.1 R1.2 U1.1
NetC1_2: C1.2 R1.1 R2.2 U1.2 | length 161.4
  Top Layer w12: R2.2@3055.72,1045.11 R1.1@3112.97,1045.11 ; U1.2@3105.37,993.61 3105.37,1037.51 R1.1@3112.97,1045.11 ; C1.2@3113.21,1094.24 3113.21,1045.98 R1.1@3113.53,1045.66 R1.1@3112.97,1045.11
NetC2_1: C2.1 C5.1 L1.2 U1.5 U1.8 | length 154.1
  Top Layer w12: v1(3025.62,883.32) 3025.68,883.37 U1.5@3054.19,883.37
  Bottom Layer w12: v1(3025.62,883.32) 3054.92,854.01 v1(3139,854.01)
NetC7_1: C7.1 U1.6 | length 41.6
  Top Layer w10: U1.6@3079.78,883.37 3079.78,845.31 C7.1@3082.29,842.8
NetC10_2: C10.2 C22.1
NetC13_1: C13.1 FB1.2 U2.4 | length 107.4
  Top Layer w10: U2.4@3216.56,1294.72 3216.56,1249.08 C13.1@3229.98,1235.66 3235.36,1230.28 FB1.2@3235.36,1195.09
NetC17_2: C17.2 C18.1
NetFB3_2: FB3.2 Q1.1 R10.2 | length 265.6
  Top Layer w20: Q1.1@610.43,1534.66 805.86,1534.66 R10.2@809.36,1531.17 815.92,1524.6 FB3.2@815.92,1468.66
NetFB4_2: FB4.2 L3.1 L4.1 R12.1 | length 3989.4
  Top Layer w10: R12.1@1673.75,1872.66 1628.36,1872.66 1611.36,1889.66 1611.36,1956.66 1629.36,1974.66 FB4.2@1686.92,1974.66
  Signal Layer 1 w0: 1738,1556.08 ccw(c1588,1556.08) 1738,1556.08 ; 2083.37,1557.23 ccw(c1933.37,1557.23) 2083.37,1557.23
  Signal Layer 2 w0: 1738.13,1556.08 ccw(c1588.13,1556.08) 1738.13,1556.08 ; 2083,1557.98 ccw(c1933,1557.98) 2083,1557.98
NetR3_1: R3.1 R4.2 | length 115.2
  Top Layer w50: R3.1@394.3,1026.39 509.37,1026.39 R4.2@509.48,1026.28
NetR4_1: R4.1 R5.2 | length 112.4
  Top Layer w50: R4.1@506.7,912.1 R5.2@619.1,912.1
NetR5_1: R5.1 R7.2 | length 110.6
  Top Layer w50: R5.1@615.13,1026.28 725.01,1026.28 R7.2@725.54,1025.75
NetR7_1: R7.1 R14.2 | length 110.4
  Top Layer w50: R7.1@725.54,911.57 R14.2@835.95,911.57
NetR14_1: R14.1 R15.2 | length 95.3
  Top Layer w50: R14.1@835.95,1025.75 839.27,1029.07 R15.2@839.27,1119.66
V_cap: J4.1 J4.2 L3.2 L4.2 | length 7539.8
  Signal Layer 1 w0: 1738.13,723.34 ccw(c1588.13,723.34) 1738.13,723.34 ; 1738.13,723.34 ccw(c1588.13,723.34) 1738.13,723.34 ; 2084.59,723.34 ccw(c1934.59,723.34) 2084.59,723.34 ; 2084.59,723.34 ccw(c1934.59,723.34) 2084.59,723.34 ; 1911.36,699.72 ccw(c1761.36,699.72) 1911.36,699.72
  Signal Layer 2 w0: 1739.01,726.01 ccw(c1589.01,726.01) 1739.01,726.01 ; 1912.24,702.39 ccw(c1762.24,702.39) 1912.24,702.39 ; 2085.47,726.01 ccw(c1935.47,726.01) 2085.47,726.01
VDDH: C11.1 C12.1 U2.15 | length 37.5
  Top Layer w10: 3162.31,1712.87 3162.31,1679.68 U2.15@3165.38,1676.61
VDDM: C11.2 C12.2 C14.1 C15.1 C16.1 U2.13 | length 219.5
  Top Layer w10: C11.2@3179.36,1874.66 3179.36,1805.66 3199.36,1785.66 3199.36,1769.26 3216.96,1751.66 C14.1@3216.56,1751.27 ; C14.1@3215.36,1755.33 3215.36,1750.83 3218,1748.18 3218,1678.04 U2.13@3216.56,1676.61
VDRV: FB3.1 TP3.1 U2.16 | length 2337.5
  Top Layer w15: TP3.1@3009.36,1674.66 3011.3,1676.61 U2.16@3139.79,1676.61
  Top Layer w20: FB3.1@886.79,1468.66 v1(921.36,1468.66)
  Bottom Layer w20: v1@922.51,1469.81 1127.36,1674.66 TP3.1@3009.36,1674.66
VSSP: C13.2 C20.2 FB2.2 TP1.1 U2.3 U2.6 U2.7 U2.8
  other v1: 3136,1199.66 3172.88,1199.66 3281.36,1243.66 3321.36,1243.66 3361.36,1243.66 3361.36,1281.16 3361.36,1318.66
VSSS: C9.2 C14.2 C15.2 C16.2 C21.2 FB4.1 TP3.2 TP6.1 U2.9 U2.10 U2.14 | length 1896.7
  Top Layer w10: FB4.1@1757.79,1974.66 1757.88,1974.75 v1(2112.22,1974.75) ; C14.2@3175.36,1755.33 3175.36,1750.83 3186.66,1739.53 3186.66,1730.34 v1(3189.3,1727.69) ; U2.14@3190.97,1676.61 3190.14,1677.44 3190.14,1726.54 v1@3190.97,1727.38
  Bottom Layer w10: v1(2112.22,1974.75) 2232.96,1854 2979.29,1854 2994.5,1838.79 3024.22,1838.79 3039.43,1854 3317.02,1854 3387,1784.02 v1(3387,1693)
  other v1: 3352,1659 3387,1658.66 3352,1692.89 3071.47,1708.66 3105.36,1708.66 3071.47,1746 3401.36,1917.66 3030.36,1980.39 3160.36,1980.39
pads on no net: FID1.1 FID2.1 FID3.1 L3.3 L3.4 L3.5 L3.6 U1.3 U1.7 U2.5
copper on no net: | length 19792
  Signal Layer 1 w0: 62.36,252.54 ccw(c82.36,252.54) 82.36,232.54 312.36,232.54 ccw(c312.36,252.54) 332.36,252.54 332.36,482.54 ccw(c312.36,482.54) 312.36,502.54 82.36,502.54 ccw(c82.36,482.54) 62.36,482.54 62.36,252.54 ; 216.02,1187.46 ccw(c87.02,1187.46) 216.02,1187.46 ; 573.87,359.66 ccw(c444.87,359.66) 573.87,359.66 ; 1015.36,1468.66 ccw(c921.36,1468.66) 1015.36,1468.66 ; 1291.24,1871.71 ccw(c1197.24,1871.71) 1291.24,1871.71 ; 1423.36,248 ccw(c1443.36,248) 1443.36,228 1673.36,228 ccw(c1673.36,248) 1693.36,248 1693.36,478 ccw(c1673.36,478) 1673.36,498 1443.36,498 ccw(c1443.36,478) 1423.36,478 1423.36,248 ; 1582.48,1871.71 ccw(c1488.48,1871.71) 1582.48,1871.71 ; 1623.29,1457.27 ccw(c1643.29,1457.27) 1643.29,1437.27 1893.29,1437.27 ccw(c1893.29,1457.27) 1913.29,1457.27 1913.29,1707.27 ccw(c1893.29,1707.27) 1893.29,1727.27 1643.29,1727.27 ccw(c1643.29,1707.27) 1623.29,1707.27 1623.29,1457.27 ; 1911.36,699.72 ccw(c1761.36,699.72) 1911.36,699.72 ; 1934.02,360.99 ccw(c1805.02,360.99) 1934.02,360.99 ; 2206.22,1974.75 ccw(c2112.22,1974.75) 2206.22,1974.75
  Signal Layer 2 w0: 57.28,245.04 ccw(c77.28,245.04) 77.28,225.04 307.28,225.04 ccw(c307.28,245.04) 327.28,245.04 327.28,475.04 ccw(c307.28,475.04) 307.28,495.04 77.28,495.04 ccw(c77.28,475.04) 57.28,475.04 57.28,245.04 ; 216.02,1185.66 ccw(c87.02,1185.66) 216.02,1185.66 ; 574.2,360.16 ccw(c445.2,360.16) 574.2,360.16 ; 1015.36,1468.66 ccw(c921.36,1468.66) 1015.36,1468.66 ; 1290.36,1872.66 ccw(c1196.36,1872.66) 1290.36,1872.66 ; 1420.17,242.7 ccw(c1440.17,242.7) 1440.17,222.7 1670.17,222.7 ccw(c1670.17,242.7) 1690.17,242.7 1690.17,472.7 ccw(c1670.17,472.7) 1670.17,492.7 1440.17,492.7 ccw(c1440.17,472.7) 1420.17,472.7 1420.17,242.7 ; 1581.36,1872.66 ccw(c1487.36,1872.66) 1581.36,1872.66 ; 1615.47,1459.02 ccw(c1635.47,1459.02) 1635.47,1439.02 1885.47,1439.02 ccw(c1885.47,1459.02) 1905.47,1459.02 1905.47,1709.02 ccw(c1885.47,1709.02) 1885.47,1729.02 1635.47,1729.02 ccw(c1635.47,1709.02) 1615.47,1709.02 1615.47,1459.02 ; 1739.01,726.01 ccw(c1589.01,726.01) 1739.01,726.01 ; 1912.24,702.39 ccw(c1762.24,702.39) 1912.24,702.39 ; 1934.17,361.08 ccw(c1805.17,361.08) 1934.17,361.08 ; 2085.47,726.01 ccw(c1935.47,726.01) 2085.47,726.01 ; 2206.22,1974.75 ccw(c2112.22,1974.75) 2206.22,1974.75

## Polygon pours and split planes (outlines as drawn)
NetFB4_2 on Top Layer "TOP_LAYER_NETFB4_2_P006" (solid, remove dead copper, pour order 6): 1639.02,1938.66 2102.36,1938.66 2303.36,1737.66 2303.36,1384.26 1678.84,1384.26 1630.36,1432.75 1630.36,1789.3 1637.89,1796.84
V_cap on Top Layer "TOP_LAYER_V_CAP_P012" (solid, remove dead copper, pour order 12): 2300.36,908 2300.36,653.11 2165.36,518.11 2165.36,91.66 2122.36,48.66 1426.81,48.66 1395.36,80.12 1395.36,543.66 1426.81,575.12 1426.81,842.81 1492,908
VSSP on Top Layer "TOP_LAYER_VSSP_P016" (solid, remove dead copper, pour order 16): 3331.96,1182.66 3468.36,1182.66 3506.36,1220.66 3506.36,1328.16 3484.86,1349.66 2882.36,1349.66 2847.36,1314.66 2847.36,1227.28 2891.36,1183.28
LDO_INPUT+ on Top Layer "TOP_LAYER_LDO_INPUT+_P014" (solid, remove dead copper, pour order 14): 3447.84,36.14 3223.5,36.14 3095.11,164.52 3095.11,659.14 3239.86,659.14 3388.34,510.66 3453.36,510.66 3584.36,379.66 3584.36,172.66
LDO_INPUT- on Top Layer "TOP_LAYER_LDO_INPUT-_P013" (solid, remove dead copper, pour order 13): 2836.36,40.66 2943.97,40.66 3072.36,169.05 3072.36,663.66 2927.61,663.66 2768.61,504.66 2727.36,504.66 2598.14,375.44 2598.14,178.88 2737.58,39.44 2835.13,39.44
LDO_GND on Top Layer "TOP_LAYER_LDO_GND_P015" (solid, remove dead copper, pour order 15): 3501.36,686.11 3063.36,686.11 2885.54,686.11 2847.36,724.3 2847.36,1094.52 2888.29,1135.45 3467.57,1135.45 3501.36,1101.66
VSSS on Top Layer "TOP_LAYER_VSSS_P025" (solid, remove dead copper, pour order 25): 3456.88,1643.14 3505.4,1691.66 3505.4,1964.62 3465.36,2004.66 2986.9,2004.66 2936.36,1954.12 2936.36,1704.66 2997.88,1643.14
-HV on Top Layer "TOP_LAYER_-HV_P024" (solid, remove dead copper, pour order 24): 640.27,1186.57 659.36,1205.66 659.36,1285.66 660.23,1285.66 704.78,1330.21 896.81,1330.21 919.23,1307.79 979.23,1307.79 979.23,1435.11 979.2,1435.13 620.83,1435.13 596.7,1411 596.7,1186.57
+IN on Top Layer "TOP_LAYER_+IN_P023" (solid, remove dead copper, pour order 23): 430.35,937.69 344.31,937.69 316.96,965.04 316.96,1129.35 63.49,1129.35 50.8,1116.66 50.8,895.23 61.24,884.8 63.42,886.98 430.72,886.98
VDDM on Top Layer "TOP_LAYER_VDDM_P017" (solid, remove dead copper, pour order 17): 3278.92,1843.16 3279.58,1843.82 3279.58,1986.16 3229.58,1986.16 3154.36,1910.94 3154.36,1843.16
LDO_OUT on Top Layer "TOP_LAYER_LDO_OUT_P011" (solid, remove dead copper, pour order 11): 3155.99,981.8 3165.86,991.66 3276.49,991.66 3320.36,991.66 3320.36,1035.66 3311.36,1044.66 3279.86,1044.66 3261.73,1062.79 3261.73,1131.39 3258.09,1135.03 3211.22,1135.03 3206.86,1130.66 3206.86,1117.66 3200.86,1111.66 3147.97,1111.66 3141.36,1105.05 3141.36,1024.16 3123.61,1006.41 3122.36,1005.16 3122.36,982.3 3122.86,981.8
NetC2_1 on Top Layer "TOP_LAYER_NETC2_1_P010" (solid, remove dead copper, pour order 10): 3124.36,893.94 3124.36,828.66 3111.36,815.66 3091.17,815.66 3082.17,806.66 3082.17,750.85 3094.36,738.66 3094.36,695.66 3103.65,686.37 3234.08,686.37 3237.36,689.65 3237.36,745.66 3219.36,763.66 3181.49,763.66 3151.86,793.29 3151.86,894.67 3146.87,899.66 3128,899.66
-HV on Top Layer "TOP_LAYER_-HV_P009" (solid, remove dead copper, pour order 9): 919.59,1436.39 919.59,797.9 719.36,597.66 719.36,76.66 747.36,48.66 748.36,49.66 1229.35,49.66 1257.64,77.94 1256.36,79.22 1256.36,557.66 1229.35,584.66 1229.35,1366.11 1160.7,1435.12
NetC17_2 on Top Layer "TOP_LAYER_NETC17_2_P008" (solid, remove dead copper, pour order 8): 404.18,1187.15 404.49,1187.46 509.76,1187.46 509.76,1273.48 509.48,1273.76 509.27,1273.55 404.18,1273.55
NetC10_2 on Top Layer "TOP_LAYER_NETC10_2_P007" (solid, remove dead copper, pour order 7): 403.78,1307.35 404.09,1307.66 509.36,1307.66 509.36,1393.69 509.08,1393.97 508.87,1393.76 403.78,1393.76
160mVcmp on Top Layer "TOP_LAYER_160MVCMP_P004" (solid, remove dead copper, pour order 4): 1358.16,1805.73 1467.06,1805.73 1467.06,1939.59 1358.43,1939.59 1358.36,1939.66
1.23Vcmp on Top Layer "TOP_LAYER_1.23VCMP_P002" (solid, remove dead copper, pour order 2): 517.91,1569.51 845.09,1569.51 864.2,1550.41 1169.06,1550.41 1177.36,1558.7 1177.36,1964.66 1162.14,1979.88 567.49,1979.88 517.91,1930.3
+IN on Top Layer "TOP_LAYER_+IN_P001" (solid, remove dead copper, pour order 1): 316.57,885.81 317.36,886.6 317.36,1393.97 331.36,1407.97 331.36,1935.66 311.36,1955.66 64.36,1955.66 48.36,1939.66 48.36,883.66
+HV on Top Layer "TOP_LAYER_+HV_P000" (solid, remove dead copper, pour order 0): 575.36,53.66 576.36,54.66 576.36,497.55 531.25,542.66 302.77,771.13 39.36,771.13 39.36,147.78 132.48,54.48
VSSP on Signal Layer 1 "SIGNAL_LAYER_1_VSSP_P018" (solid, remove dead copper, pour order 18): 3332.01,1183.73 3468.4,1183.73 3506.4,1221.73 3506.4,1329.23 3484.9,1350.73 2882.4,1350.73 2847.4,1315.73 2847.4,1228.35 2891.4,1184.35
LDO_INPUT- on Signal Layer 1 "SIGNAL_LAYER_1_LDO_INPUT-_P030" (solid, remove dead copper, pour order 30): 2834.12,39.1 3450.13,39.1 3584.58,173.55 3584.58,518.44 3440.92,662.1 2746.8,662.1 2595.9,511.21 2595.9,177.32 2735.34,37.88 2832.9,37.88
-HV on Signal Layer 1 "SIGNAL_LAYER_1_-HV_P026" (solid, remove dead copper, pour order 26): 2355.62,49.31 2475.36,169.05 2475.36,1857.66 2322.36,2010.66 83.36,2010.66 38.36,1965.66 38.36,96.66 82.28,52.74
LDO_GND on Signal Layer 1 "SIGNAL_LAYER_1_LDO_GND_P031" (solid, remove dead copper, pour order 31): 3500.98,685.82 3062.98,685.82 2885.16,685.82 2846.98,724 2846.98,1094.22 2887.91,1135.15 3467.19,1135.15 3500.98,1101.36
VSSS on Signal Layer 1 "SIGNAL_LAYER_1_VSSS_P027" (solid, remove dead copper, pour order 27): 3456.71,1642.82 3505.23,1691.34 3505.23,1964.29 3465.19,2004.34 2986.73,2004.34 2936.19,1953.8 2936.19,1704.34 2997.71,1642.82
VSSP on Signal Layer 2 "SIGNAL_LAYER_2_VSSP_P019" (solid, remove dead copper, pour order 19): 3332.01,1183.89 3468.4,1183.89 3506.4,1221.89 3506.4,1329.39 3484.9,1350.89 2882.4,1350.89 2847.4,1315.89 2847.4,1228.51 2891.4,1184.51
LDO_INPUT- on Signal Layer 2 "SIGNAL_LAYER_2_LDO_INPUT-_P032" (solid, remove dead copper, pour order 32): 2833.12,40.96 3449.13,40.96 3583.58,175.41 3583.58,520.3 3439.92,663.96 2745.8,663.96 2594.9,513.06 2594.9,179.18 2734.34,39.74 2831.9,39.74
-HV on Signal Layer 2 "SIGNAL_LAYER_2_-HV_P043" (solid, remove dead copper, pour order 43): 2349.01,46.32 2476.36,173.66 2476.36,1861.66 2330.36,2007.66 81.36,2007.66 36.36,1962.66 36.36,93.66 80.28,49.74
LDO_GND on Signal Layer 2 "SIGNAL_LAYER_2_LDO_GND_P033" (solid, remove dead copper, pour order 33): 3499.98,687.67 3061.98,687.67 2884.16,687.67 2845.98,725.86 2845.98,1096.08 2886.91,1137.01 3466.19,1137.01 3499.98,1103.22
VSSS on Signal Layer 2 "SIGNAL_LAYER_2_VSSS_P044" (solid, remove dead copper, pour order 44): 3458.24,1647.82 3506.76,1696.34 3506.76,1969.29 3466.71,2009.34 2988.25,2009.34 2937.71,1958.8 2937.71,1709.34 2999.23,1647.82
VSSP on Signal Layer 3 "SIGNAL_LAYER_3_VSSP_P020" (solid, remove dead copper, pour order 20): 3332.01,1183.89 3468.4,1183.89 3506.4,1221.89 3506.4,1329.39 3484.9,1350.89 2882.4,1350.89 2847.4,1315.89 2847.4,1228.51 2891.4,1184.51
LDO_INPUT- on Signal Layer 3 "SIGNAL_LAYER_3_LDO_INPUT-_P034" (solid, remove dead copper, pour order 34): 2835.12,40.96 3451.13,40.96 3585.58,175.41 3585.58,520.3 3441.92,663.96 2747.8,663.96 2596.9,513.06 2596.9,179.18 2736.34,39.74 2833.9,39.74
VSSS on Signal Layer 3 "SIGNAL_LAYER_3_VSSS_P041" (solid, remove dead copper, pour order 41): 3454.2,1644.44 3506.2,1696.44 3506.2,1965.44 3461.2,2010.44 595.75,2010.44 515.2,1929.89 515.2,1512.44 787.2,1240.44 2185.79,1240.44 2596.2,1650.85
LDO_GND on Signal Layer 3 "SIGNAL_LAYER_3_LDO_GND_P035" (solid, remove dead copper, pour order 35): 3501.98,687.67 3063.98,687.67 2886.16,687.67 2847.98,725.86 2847.98,1096.08 2888.91,1137.01 3468.19,1137.01 3501.98,1103.22
VSSP on Signal Layer 4 "SIGNAL_LAYER_4_VSSP_P021" (solid, remove dead copper, pour order 21): 3332.01,1184.73 3468.4,1184.73 3506.4,1222.73 3506.4,1330.23 3484.9,1351.73 2882.4,1351.73 2847.4,1316.73 2847.4,1229.35 2891.4,1185.35
LDO_INPUT- on Signal Layer 4 "SIGNAL_LAYER_4_LDO_INPUT-_P036" (solid, remove dead copper, pour order 36): 2833.12,38.96 3449.13,38.96 3583.58,173.41 3583.58,518.3 3439.92,661.96 2745.8,661.96 2594.9,511.06 2594.9,177.18 2734.34,37.74 2831.9,37.74
VSSS on Signal Layer 4 "SIGNAL_LAYER_4_VSSS_P040" (solid, remove dead copper, pour order 40): 3458.15,1644.69 3510.15,1696.69 3510.15,1965.69 3465.15,2010.69 599.7,2010.69 519.15,1930.14 519.15,1512.69 791.15,1240.69 2189.74,1240.69 2600.15,1651.1
LDO_GND on Signal Layer 4 "SIGNAL_LAYER_4_LDO_GND_P037" (solid, remove dead copper, pour order 37): 3499.98,685.67 3061.98,685.67 2884.16,685.67 2845.98,723.86 2845.98,1094.08 2886.91,1135.01 3466.19,1135.01 3499.98,1101.22
VSSP on Bottom Layer "BOTTOM_LAYER_VSSP_P022" (solid, remove dead copper, pour order 22): 3331.01,1183.89 3467.4,1183.89 3505.4,1221.89 3505.4,1329.39 3483.9,1350.89 2881.4,1350.89 2846.4,1315.89 2846.4,1228.51 2890.4,1184.51
LDO_INPUT- on Bottom Layer "BOTTOM_LAYER_LDO_INPUT-_P038" (solid, remove dead copper, pour order 38): 2837.12,38.96 3453.13,38.96 3587.58,173.41 3587.58,518.3 3443.92,661.96 2749.8,661.96 2598.9,511.06 2598.9,177.18 2738.34,37.74 2835.9,37.74
VSSS on Bottom Layer "BOTTOM_LAYER_VSSS_P045" (solid, remove dead copper, pour order 45): 3458.09,1644.74 3510.09,1696.74 3510.09,1965.74 3465.09,2010.74 599.64,2010.74 519.09,1930.19 519.09,1512.74 791.09,1240.74 2189.68,1240.74 2600.09,1651.15
LDO_GND on Bottom Layer "BOTTOM_LAYER_LDO_GND_P039" (solid, remove dead copper, pour order 39): 3503.98,685.67 3065.98,685.67 2888.16,685.67 2849.98,723.86 2849.98,1094.08 2890.91,1135.01 3470.19,1135.01 3503.98,1101.22

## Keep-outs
Keep-Out Layer:
  text ".Layer_Name" at 580.02,-820.56 h60

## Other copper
Top Layer:
  region net VDDH: 3164.36,1801.61 3164.36,1777.35 3158.49,1771.48 3158.49,1733.73 3173.45,1714.82 3173.45,1644.35 3172.24,1643.14 3158.49,1643.14 3157.31,1644.32 3157.31,1713.85 3074.36,1796.8 3074.43,1814.24 3074.36,1814.31 3074.36,1875.66 3122.86,1875.66 3124.36,1877.16 3124.36,1824.95 3144.65,1804.66 3161.31,1804.66
  text ".Layer_Name" at 580.02,-820.56 h60
Bottom Layer:
  text ".Layer_Name" at 580.02,-820.56 h60

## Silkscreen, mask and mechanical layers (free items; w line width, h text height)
Top Overlay:
  text ".PRJ_Number" at 1941.36,1807.66 h60
  text "HV-" at 883.85,545.02 h100
  text "HV+" at 211.49,542.02 h100
  text "-" at 2959.93,312.74 h100
  text "+" at 3185.61,304.46 h100
  text "LINK+" at 1939.2,258.66 h100
  text "Maximum DC Input / 5V - 36V / 50 mA" at 2813.55,-12.08 h60
  text "Maximum DC Output / 1200V / 5.5A" at 1907.36,-25.08 h60
Top Paste:
  text ".Layer_Name" at 580.02,-820.56 h60
Bottom Paste:
  text ".Layer_Name" at 580.02,-820.56 h60
Top Solder:
  text ".Layer_Name" at 580.02,-820.56 h60
  text ".Layer_Name" at 580.02,-820.56 h60
Bottom Solder:
  text ".Layer_Name" at 580.02,-820.56 h60
Drill Guide:
  text ".Layer_Name" at 580.02,-820.56 h60
M1 Board Outline:
  the board outline again, w10
  text ".Layer_Name" at 580.02,-820.56 h60
M2 Board Dimensions:
  rectangle: 3.02,-237.06 128.02,-112.06
  rectangle: 128.02,-362.06 503.02,-237.06
  lines w7: 3.02,-237.06 1003.02,-237.06 ; 128.02,-362.06 128.02,-112.06 ; 253.02,-362.06 253.02,-112.06 ; 503.02,-362.06 503.02,-112.06 ; 753.02,-362.06 753.02,-112.06 ; 3.02,-362.06 1003.02,-362.06 1003.02,-112.06 3.02,-112.06 3.02,-362.06
  text ".Layer_Name" at 580.02,-820.56 h60
M3 3D STEP Top:
  text ".Layer_Name" at 580.02,-820.56 h60
M4 3D STEP Bottom:
  text ".Layer_Name" at 580.02,-820.56 h60
M5 Assembly Top:
  lines w10: -288.98,-892.23 6311.02,-892.23 ; -288.98,-688.9 6313.02,-688.9 ; -288.98,-485.56 -288.98,-1095.56 3716.02,-1095.56 6313.02,-1095.56 6313.02,-485.56 -288.48,-485.56 -288.48,-1095.56 1287.02,-1095.56 ; 2176.02,-1095.56 2176.02,-485.56 ; 3443.02,-688.9 3443.02,-485.56 ; 4283.02,-688.9 4283.02,-485.56 ; 4905.02,-1102.06 4905.02,-899.23
  text "COMPONENTS MARKED 'DNP' SHOULD NOT BE POPULATED." at 1156.52,-280.56 h60
  text "ASSEMBLY VARIANT:" at 1156.02,-396.06 h60
  text ".VariantName" at 2192.02,-396.06 h60
  text "PCB VIEWED FROM TOP SIDE" at -225.48,-617.73 h60
  text "BOARD #:" at 2251.02,-617.73 h60
  text ".PRJ_Number" at 2796.52,-617.73 h60
  text "REV:" at 3641.02,-617.73 h60
  text ".PCB_Rev" at 3932.52,-617.73 h60
  text "SVN REV:" at 4479.02,-617.73 h60
  text ".VersionControl_RevNumber" at 4985.02,-617.73 h60
  text "TID #:" at 2251.02,-821.06 h60
  text ".TID" at 2796.52,-821.06 h60
  text "PLOT NAME =" at -225.48,-1026.4 h60
  text ".plot_File_Name" at 580.02,-1026.4 h60
  text "GENERATED    :" at 2253.02,-1026.4 h60
  text ".Print_Date" at 3122.52,-1026.4 h60
  text ".Print_Time" at 3851.52,-1026.4 h60
  text "TEXAS INSTRUMENTS" at 5116.02,-1026.4 h60
M6 Assembly Bottom:
  lines w10: -289.48,-689.4 6312.52,-689.4 ; -287.48,-892.73 6312.52,-892.73 ; 1118.52,-1102.56 1118.52,-899.73 ; 1740.52,-689.4 1740.52,-486.06 ; 2580.52,-689.4 2580.52,-486.06 ; 3847.52,-1096.06 3847.52,-486.06 ; 4736.52,-1096.06 6312.02,-1096.06 6312.02,-486.06 -289.48,-486.06 -289.48,-1096.06 2307.52,-1096.06 6312.52,-1096.06 6312.52,-486.06
  text "COMPONENTS MARKED 'DNP' SHOULD NOT BE POPULATED." at 6105.02,-280.06 h60
  text ".VariantName" at 5061.02,-396.06 h60
  text "ASSEMBLY VARIANT:" at 6100.02,-396.06 h60
  text ".VersionControl_RevNumber" at 1038.52,-618.23 h60
  text "SVN REV:" at 1544.52,-618.23 h60
  text ".PCB_Rev" at 2091.02,-618.23 h60
  text "REV:" at 2382.52,-618.23 h60
  text ".PRJ_Number" at 3227.02,-618.23 h60
  text "BOARD #:" at 3772.52,-618.23 h60
  text "PCB VIEWED FROM BOTTOM SIDE" at 6249.02,-618.23 h60
  text ".TID" at 3227.02,-821.56 h60
  text "TID #:" at 3772.52,-821.56 h60
  text "TEXAS INSTRUMENTS" at 907.52,-1026.9 h60
  text ".Print_Time" at 2172.02,-1026.9 h60
  text ".Print_Date" at 2901.02,-1026.9 h60
  text "GENERATED    :" at 3770.52,-1026.9 h60
  text ".plot_File_Name" at 5443.52,-1026.9 h60
  text "PLOT NAME =" at 6249.02,-1026.9 h60
M9 Title Sheet:
  drawing of 57 lines, arcs and shapes, not listed
  text "1" at 742.86,8074.44 h70
  text "2" at 3238.52,8074.44 h70
  text "3" at 5727.87,8074.44 h70
  text "4" at 8234.53,8074.44 h70
  text "5" at 10733.52,8074.44 h70
  text "6" at 13238.52,8074.44 h70
  text "A" at -413.48,6931.44 h70
  text "A" at 14386.52,6931.44 h70
  text "B" at -413.48,4551.44 h70
  text "B" at 14386.52,4551.44 h70
  text "C" at -413.48,2176.44 h70
  text "C" at 14386.52,2176.44 h70
  text "PROJECT TITLE:" at 11346.52,315.44 h45
  text ".PRJ_Title" at 11396.52,182.11 h70
  text "DESIGNED FOR:" at 11346.52,14.44 h45
  text ".PRJ_Customer" at 11396.52,-125.56 h70
  text "D" at -413.48,-193.56 h70
  text "D" at 14386.52,-193.56 h70
  text "FILE NAME:" at 11346.52,-285.56 h45
  text ".PCB_File_Name_No_Path" at 11396.52,-405.56 h70
  text "Texas Instruments (TI) and/or its licensors do not warrant the accuracy or completeness of this specification" at 6377.02,-567.4 h45
  text "ENGINEER:" at 11346.52,-575.56 h45
  text "LAYOUT BY:" at 12851.52,-575.56 h45
  text "or any information contained therein. TI and/or its licensors do not warrant that this design will meet" at 6332.04,-680.07 h45
  text ".PRJ_Engineer" at 11396.52,-730.56 h70
  text ".PCB_Layout" at 12902.02,-730.56 h70
  text "the specifications, will be suitable for your application or fit for any particular purpose, or will operate in" at 6332.04,-792.73 h45
  text ".Layer_Name" at 580.02,-820.56 h60
  text "ALTIUM DESIGNER VERSION:" at 12851.52,-885.56 h45
  text "an implementation. TI and/or its licensors do not warrant that the design is production worthy. You should" at 6332.04,-905.4 h45
  text "completely validate and test your design implementation to confirm the system functionality for your application." at 6377.02,-1018.06 h45
  text ".print_Scale" at 11396.52,-1018.89 h70
  text ".Application_BuildNumber" at 12902.02,-1018.89 h70
  text "1" at 742.86,-1225.56 h70
  text "2" at 3238.52,-1225.56 h70
  text "3" at 5727.87,-1225.56 h70
  text "4" at 8234.53,-1225.56 h70
  text "5" at 10733.52,-1225.56 h70
  text "6" at 13238.52,-1225.56 h70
